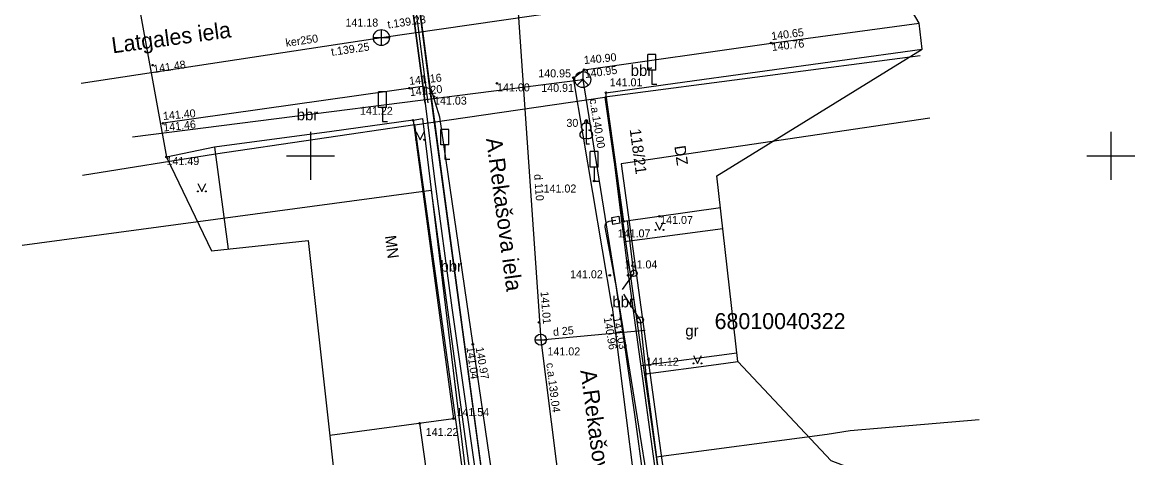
# Model space of a CAD drawing. Extents: x 728710 to 728960, y 272811 to 273475.
# Drawn here: x 728782 to 728851.5, y 273131.1 to 273158.4 of the extents above; entities that cross this region are included whole.
import ezdxf

# ---------------------------------------------------------------- set-up
doc = ezdxf.new("R2010")
doc.units = 0
for name, color, linetype in [('54', 7, 'Continuous'), ('58', 7, 'Continuous'), ('GEOD_ELEM_####_TKST_#', 7, 'Continuous'), ('Level 10', 7, 'Continuous'), ('Level 15', 7, 'Continuous'), ('Level 17', 7, 'Continuous'), ('Level 23', 7, 'Continuous'), ('Level 27', 7, 'Continuous'), ('Level 29', 7, 'Continuous'), ('Level 3', 7, 'Continuous'), ('Level 36', 7, 'Continuous'), ('Level 38', 7, 'Continuous'), ('Level 39', 7, 'Continuous'), ('Level 4', 7, 'Continuous'), ('Level 41', 7, 'Continuous'), ('Level 43', 7, 'Continuous'), ('Level 46', 7, 'Continuous'), ('Level 48', 7, 'Continuous'), ('Level 49', 7, 'Continuous'), ('Level 54', 7, 'Continuous'), ('Level 55', 7, 'Continuous'), ('Level 56', 7, 'Continuous'), ('Level 57', 7, 'Continuous'), ('Level 58', 7, 'Continuous'), ('Level 59', 7, 'Continuous'), ('Level 60', 7, 'Continuous'), ('Level 62', 7, 'Continuous'), ('PNTNO', 7, 'Continuous'), ('RAMI_UZMR_####_####_#', 7, 'Continuous'), ('RELJ_ELEM_####_####_#', 7, 'Continuous'), ('RELJ_NOGA_####_####_#', 7, 'Continuous'), ('ROBZ_ELEM_####_####_#', 7, 'Continuous'), ('ROBZ_KADS_####_TKST_#', 7, 'Continuous'), ('ROBZ_UZMR_####_####_#', 7, 'Continuous'), ('TERT_ELEM_####_####_#', 7, 'Continuous'), ('TERT_KONT_####_####_#', 7, 'Continuous')]:
    doc.layers.add(name, color=color, linetype=linetype)

msp = doc.modelspace()

# ---------------------------------------------------------------- linework, layer by layer
at = {"layer": 'GEOD_ELEM_####_TKST_#'}
msp.add_lwpolyline([(728812.551, 273107.084), (728813.681, 273107.292), (728813.683, 273107.676), (728812.175, 273119.32), (728807.481, 273154.061), (728806.142, 273164.357), (728806.065, 273164.722), (728806.247, 273164.866), (728807.003, 273165.091)], dxfattribs=at)
at = {"layer": 'Level 10'}
for p, q in [((728800, 273151.5), (728800, 273150)), ((728850, 273151.5), (728850, 273150)), ((728798.5, 273150), (728800, 273150)), ((728800, 273150), (728800, 273148.5)), ((728800, 273150), (728801.5, 273150)), ((728848.5, 273150), (728850, 273150)), ((728850, 273150), (728850, 273148.5)), ((728850, 273150), (728851.5, 273150))]:
    msp.add_line(p, q, dxfattribs=at)
at = {"layer": 'Level 15'}
msp.add_lwpolyline([(728819.334, 273145.797), (728818.894, 273145.717), (728818.816, 273146.149), (728819.256, 273146.229)], close=True, dxfattribs=at)
at = {"layer": 'Level 17'}
msp.add_line((728814.387, 273138.519), (728820.906, 273139.113), dxfattribs=at)
for points in [[(728812.761, 273161.966), (728814.387, 273138.519)], [(728814.387, 273138.519), (728819.492, 273098.009)]]:
    msp.add_lwpolyline(points, dxfattribs=at)
at = {"layer": 'Level 23'}
msp.add_lwpolyline([(728785.659, 273154.554), (728804.423, 273157.397), (728830.532, 273161.186)], dxfattribs=at)
at = {"layer": 'Level 27'}
for points in [[(728820.21, 273142.669), (728819.812, 273145.946)], [(728820.595, 273139.749), (728820.949, 273136.385)]]:
    msp.add_lwpolyline(points, dxfattribs=at)
at = {"layer": 'Level 29'}
for p, q in [((728803.923, 273157.397), (728804.923, 273157.397)), ((728804.423, 273156.897), (728804.423, 273157.897))]:
    msp.add_line(p, q, dxfattribs=at)
msp.add_circle((728804.423, 273157.397), 0.5, dxfattribs=at)
at = {"layer": 'Level 3'}
for p, q in [((728822.792, 273154.55), (728838.211, 273156.68)), ((728818.457, 273153.951), (728822.792, 273154.55)), ((728819.568, 273145.912), (728818.457, 273153.951)), ((728806.402, 273152.228), (728801.322, 273151.539)), ((728806.402, 273152.228), (728808.931, 273133.58)), ((728801.322, 273151.539), (728793.998, 273150.545)), ((728793.998, 273150.545), (728794.861, 273144.179)), ((728825.616, 273146.748), (728819.568, 273145.912)), ((728820.949, 273136.385), (728825.344, 273136.966)), ((728825.344, 273136.966), (728826.701, 273137.145)), ((728822.25, 273126.539), (728820.949, 273136.385)), ((728808.931, 273133.58), (728801.201, 273132.532)), ((728806.814, 273133.293), (728808.351, 273122.364))]:
    msp.add_line(p, q, dxfattribs=at)
at = {"layer": 'Level 36'}
msp.add_line((728807.355, 273153.329), (728806.056, 273163.207), dxfattribs=at)
for points in [[(728807.157, 273153.303), (728805.858, 273163.181)], [(728818.916, 273142.762), (728819.077, 273141.897), (728820.259, 273133.689), (728821.3, 273126.022), (728821.336, 273125.784), (728822.279, 273119.148)]]:
    msp.add_lwpolyline(points, dxfattribs=at)
at = {"layer": 'Level 38'}
for p, q in [((728828.784, 273157.056), (728838.026, 273158.297)), ((728817.1, 273155.387), (728828.784, 273157.056)), ((728806.989, 273154.338), (728790.784, 273152.04))]:
    msp.add_line(p, q, dxfattribs=at)
at = {"layer": 'Level 39'}
for p, q in [((728814.036, 273138.519), (728814.738, 273138.519)), ((728814.386, 273138.519), (728814.386, 273138.52))]:
    msp.add_line(p, q, dxfattribs=at)
msp.add_circle((728814.387, 273138.519), 0.351, dxfattribs=at)
at = {"layer": 'Level 4'}
for p, q in [((728816.423, 273154.886), (728817.1, 273155.387)), ((728818.846, 273140.542), (728816.423, 273154.886)), ((728819.87, 273142.614), (728818.457, 273153.951)), ((728806.402, 273152.228), (728807.002, 273152.348)), ((728807.002, 273152.348), (728810.246, 273125.587)), ((728793.998, 273150.545), (728790.999, 273149.932)), ((728819.616, 273144.651), (728825.761, 273145.463)), ((728823.17, 273118.565), (728819.87, 273142.614)), ((728820.652, 273136.912), (728826.638, 273137.702))]:
    msp.add_line(p, q, dxfattribs=at)
for points in [[(728811.836, 273126.782), (728808.082, 273152.433), (728807.534, 273154.175), (728806.989, 273154.338)], [(728818.846, 273140.542), (728820.596, 273126.711), (728822.052, 273116.462)]]:
    msp.add_lwpolyline(points, dxfattribs=at)
at = {"layer": 'Level 41'}
msp.add_lwpolyline([(728788.876, 273151.188), (728817.008, 273154.772), (728824.535, 273107.953), (728843.792, 273111.191)], dxfattribs=at)
at = {"layer": 'Level 43'}
for p, q in [((728820.21, 273142.669), (728819.481, 273141.65)), ((728820.595, 273139.749), (728819.57, 273141.357))]:
    msp.add_line(p, q, dxfattribs=at)
for centre in [(728820.21, 273142.669), (728820.595, 273139.749)]:
    msp.add_circle(centre, 0.202, dxfattribs=at)
at = {"layer": 'Level 46'}
msp.add_line((728817.008, 273154.772), (728817.362, 273154.418), dxfattribs=at)
msp.add_lwpolyline([(728817.008, 273155.272), (728817.008, 273154.772), (728816.654, 273154.418)], dxfattribs=at)
msp.add_circle((728817.008, 273154.772), 0.5, dxfattribs=at)
at = {"layer": 'Level 48'}
for centre in [(728828.784, 273157.056), (728790.133, 273155.674), (728817.1, 273155.387), (728811.656, 273154.535), (728816.423, 273154.886), (728817.008, 273154.772), (728806.177, 273154.237), (728818.457, 273153.951), (728807.716, 273153.708), (728790.784, 273152.04), (728806.402, 273152.228), (728790.999, 273149.932), (728817.719, 273148.429), (728821.801, 273146.221), (728819.568, 273145.912), (728818.698, 273142.537), (728819.847, 273142.537), (728818.846, 273140.041), (728814.273, 273139.597), (728810.141, 273138.225), (728820.949, 273136.385), (728806.814, 273133.293), (728808.931, 273133.58)]:
    msp.add_circle(centre, 0.05, dxfattribs=at)
at = {"layer": 'Level 49'}
for p, q in [((728821.572, 273156.338), (728821.072, 273156.338)), ((728821.072, 273155.369), (728821.072, 273156.338)), ((728821.572, 273155.369), (728821.572, 273156.338)), ((728821.572, 273155.369), (728821.072, 273155.369)), ((728821.326, 273155.369), (728821.326, 273154.491)), ((728804.737, 273154.004), (728804.237, 273154.004)), ((728804.237, 273153.035), (728804.237, 273154.004)), ((728804.737, 273153.035), (728804.737, 273154.004)), ((728821.326, 273154.491), (728821.641, 273154.491)), ((728804.737, 273153.035), (728804.237, 273153.035)), ((728804.491, 273153.035), (728804.491, 273152.157)), ((728804.491, 273152.157), (728804.806, 273152.157)), ((728808.631, 273151.655), (728808.131, 273151.655)), ((728808.131, 273150.686), (728808.131, 273151.655)), ((728808.631, 273150.686), (728808.631, 273151.655)), ((728808.631, 273150.686), (728808.131, 273150.686)), ((728808.385, 273150.686), (728808.385, 273149.808)), ((728808.385, 273149.808), (728808.7, 273149.808)), ((728817.965, 273150.276), (728817.465, 273150.276)), ((728817.465, 273149.307), (728817.465, 273150.276)), ((728817.965, 273149.307), (728817.965, 273150.276)), ((728817.965, 273149.307), (728817.465, 273149.307)), ((728817.719, 273149.307), (728817.719, 273148.429)), ((728817.719, 273148.429), (728818.034, 273148.429))]:
    msp.add_line(p, q, dxfattribs=at)
at = {"layer": 'RAMI_UZMR_####_####_#'}
for points in [[(728848.126, 273018.981), (728842.745, 273067.512), (728841.027, 273070.984), (728840.357, 273077.286), (728837.229, 273086.616), (728846.28, 273097.37), (728843.445, 273113.117), (728841.542, 273127.507), (728832.527, 273130.942), (728826.701, 273137.145), (728825.388, 273148.763), (728838.211, 273156.68), (728838.026, 273158.297), (728833.202, 273166.507)], [(728788.892, 273161.497), (728790.999, 273149.932), (728793.805, 273144.064), (728799.858, 273144.727), (728801.765, 273127.417), (728785.623, 273117.349), (728785.888, 273114.234), (728788.818, 273102.829), (728792.114, 273090.001), (728794.527, 273084.256), (728808.426, 273087.287), (728810.894, 273070.336), (728816.634, 273032.011)]]:
    msp.add_lwpolyline(points, dxfattribs=at)
at = {"layer": 'RELJ_ELEM_####_####_#'}
msp.add_lwpolyline([(728807.003, 273165.091), (728806.309, 273164.885), (728806.073, 273164.759), (728806.082, 273164.765), (728806.142, 273164.357), (728807.497, 273153.999), (728812.666, 273115.604), (728813.66, 273107.967), (728813.707, 273107.385), (728813.681, 273107.292), (728813.602, 273107.257), (728812.551, 273107.084)], dxfattribs=at)
at = {"layer": 'ROBZ_ELEM_####_####_#'}
for points in [[(728838.703, 273152.369), (728819.408, 273149.515)], [(728819.408, 273149.515), (728824.842, 273109.886)], [(728807.526, 273147.836), (728781.985, 273144.395)], [(728807.526, 273147.836), (728813.011, 273107.831)]]:
    msp.add_lwpolyline(points, dxfattribs=at)
at = {"layer": 'ROBZ_UZMR_####_####_#'}
for p, q in [((728838.082, 273156.252), (728818.395, 273153.682)), ((728806.506, 273151.952), (728818.395, 273153.682)), ((728818.395, 273153.682), (728819.556, 273145.531)), ((728806.506, 273151.952), (728794.058, 273150.104)), ((728809.109, 273133.219), (728806.506, 273151.952)), ((728794.058, 273150.104), (728785.756, 273148.773)), ((728819.556, 273145.531), (728821.586, 273131.187)), ((728812.63, 273106.926), (728809.109, 273133.219)), ((728833.717, 273132.846), (728841.771, 273133.527)), ((728821.586, 273131.187), (728832.287, 273132.612)), ((728832.287, 273132.612), (728833.717, 273132.846)), ((728821.586, 273131.187), (728822.26, 273126.26))]:
    msp.add_line(p, q, dxfattribs=at)
at = {"layer": 'TERT_ELEM_####_####_#'}
for points in [[(728805.858, 273163.181), (728807.157, 273153.303)], [(728807.157, 273153.303), (728807.729, 273148.716), (728808.834, 273140.506), (728809.798, 273133.659), (728810.998, 273125.369), (728811.313, 273123.197)], [(728818.397, 273145.555), (728819.077, 273141.897), (728820.259, 273133.689), (728821.3, 273126.022), (728822.228, 273119.505)], [(728819.075, 273145.973), (728818.646, 273145.906)]]:
    msp.add_lwpolyline(points, dxfattribs=at)
msp.add_arc((728818.692, 273145.609), 0.3, 98.90447, 190.52618, dxfattribs=at)
at = {"layer": 'TERT_KONT_####_####_#'}
for p, q in [((728806.605, 273151.515), (728806.855, 273151.015)), ((728806.855, 273151.015), (728807.105, 273151.515)), ((728817.229, 273151.113), (728817.229, 273150.766)), ((728817.229, 273150.766), (728817.429, 273150.766)), ((728792.955, 273148.287), (728793.205, 273147.787)), ((728793.205, 273147.787), (728793.455, 273148.287)), ((728821.548, 273145.879), (728821.798, 273145.379)), ((728821.798, 273145.379), (728822.048, 273145.879)), ((728823.92, 273137.539), (728824.17, 273137.039)), ((728824.17, 273137.039), (728824.42, 273137.539))]:
    msp.add_line(p, q, dxfattribs=at)
for points in [[(728817.229, 273152.266), (728817.229, 273151.113)], [(728817.319, 273152.034), (728817.318, 273152.035)]]:
    msp.add_lwpolyline(points, dxfattribs=at)
for centre, radius in [((728806.605, 273151.015), 0.028), ((728807.105, 273151.015), 0.0263), ((728792.955, 273147.787), 0.028), ((728793.455, 273147.787), 0.0263), ((728821.548, 273145.378), 0.028), ((728822.048, 273145.378), 0.0263), ((728823.92, 273137.038), 0.028), ((728824.42, 273137.038), 0.0263)]:
    msp.add_circle(centre, radius, dxfattribs=at)
for centre, major_axis, ratio, start_param, end_param in [((728817.101, 273151.821), (-0.039, -0.212), 0.861323, 3.141593, 6.283185), ((728817.229, 273152.116), (0, -0.15), 0.707107, 3.14537, 5.287485), ((728817.229, 273152.116), (0, -0.15), 0.707107, 0.995701, 3.137816), ((728817.357, 273151.821), (0.039, -0.212), 0.861323, 0, 3.141593), ((728817.139, 273151.359), (0.307, 0.095), 0.814445, 1.570796, 4.752015), ((728817.319, 273151.359), (-0.307, 0.095), 0.814445, 1.531171, 4.712389)]:
    msp.add_ellipse(centre, major_axis=major_axis, ratio=ratio, start_param=start_param, end_param=end_param, dxfattribs=at)

# ---------------------------------------------------------------- texts
at = {"layer": '54'}
msp.add_text('c.a.140.00', height=0.5, rotation=279.13318, dxfattribs=at).set_placement((728817.428, 273153.529))
at = {"layer": '58'}
msp.add_text(' 140.95', height=0.5, dxfattribs=at).set_placement((728814.044, 273154.913))
at = {"layer": 'Level 54'}
for s, rotation, p in [('Latgales iela', 7.723, (728787.637, 273156.409)), ('A.Rekašova iela', 277.641, (728810.965, 273151.073)), ('A.Rekašova iela', 277.641, (728816.855, 273136.586))]:
    msp.add_text(s, height=1, rotation=rotation, dxfattribs=at).set_placement(p)
at = {"layer": 'Level 55'}
for s, rotation, p in [('d 110', 273.96699, (728813.971, 273148.847)), ('d 25', 5.20632, (728815.17, 273138.749)), ('c.a.139.04', 277.18245, (728814.724, 273137.044))]:
    msp.add_text(s, height=0.5, rotation=rotation, dxfattribs=at).set_placement(p)
at = {"layer": 'Level 56'}
msp.add_text(' 141.18', height=0.5, dxfattribs=at).set_placement((728801.997, 273158.086))
at = {"layer": 'Level 57'}
for s, rotation, p in [('140.65', 7.28083, (728828.82, 273157.238)), ('140.76', 6.56448, (728828.841, 273156.559)), ('141.48', 8.61156, (728790.208, 273155.18)), ('140.90', 5.44471, (728817.101, 273155.742)), ('140.95', 7.83534, (728817.166, 273154.864)), ('141.16', 6.10769, (728806.182, 273154.438)), ('141.20', 5.8857, (728806.222, 273153.736)), ('141.40', 5.0837, (728790.799, 273152.247)), ('141.46', 6.16242, (728790.823, 273151.525)), ('141.01', 274.5599, (728814.369, 273141.515)), ('140.96', 279.69895, (728818.314, 273139.875)), ('141.03', 282.06435, (728818.87, 273139.883)), ('141.04', 277.94442, (728809.743, 273138.041)), ('140.97', 279.92477, (728810.312, 273138.015))]:
    msp.add_text(s, height=0.5, rotation=rotation, dxfattribs=at).set_placement(p)
for s, p in [(' 141.01', (728818.506, 273154.352)), ('141.00', (728811.656, 273154.035)), ('140.91', (728814.413, 273154.007)), ('141.03', (728807.716, 273153.208)), (' 141.22', (728802.903, 273152.572)), ('141.49', (728790.999, 273149.432)), (' 141.02', (728814.376, 273147.715)), (' 141.07', (728821.661, 273145.749)), (' 141.07', (728819.006, 273144.912)), (' 141.04', (728819.44, 273142.972)), (' 141.02', (728816.031, 273142.357)), (' 141.12', (728820.774, 273136.891)), (' 141.54', (728808.93, 273133.741)), (' 141.22', (728807.011, 273132.499))]:
    msp.add_text(s, height=0.5, dxfattribs=at).set_placement(p)
at = {"layer": 'Level 58'}
for s, p in [('bbr', (728819.999, 273154.996)), ('bbr', (728799.133, 273152.231)), ('bbr', (728808.117, 273142.767)), ('bbr', (728818.856, 273140.537)), ('gr', (728823.417, 273138.734))]:
    msp.add_text(s, height=0.7, dxfattribs=at).set_placement(p)
at = {"layer": 'Level 59'}
for s, rotation, p in [('DZ', 277.866, (728822.73, 273150.604)), ('MN', 277.723, (728804.642, 273144.992))]:
    msp.add_text(s, height=0.7, rotation=rotation, dxfattribs=at).set_placement(p)
at = {"layer": 'Level 60'}
for s, p in [('t.139.23', (728804.84, 273157.963)), ('ker250', (728798.476, 273156.82)), ('t.139.25', (728801.322, 273156.252))]:
    msp.add_text(s, height=0.5, rotation=8.258, dxfattribs=at).set_placement(p)
at = {"layer": 'Level 62'}
msp.add_text('118/21', height=0.7, rotation=277.866, dxfattribs=at).set_placement((728819.936, 273151.657))
at = {"layer": 'PNTNO'}
msp.add_text(' 141.02', height=0.5, dxfattribs=at).set_placement((728814.619, 273137.537))
at = {"layer": 'RELJ_NOGA_####_####_#'}
msp.add_text('30', height=0.5, dxfattribs=at).set_placement((728815.988, 273151.817))
at = {"layer": 'ROBZ_KADS_####_TKST_#'}
msp.add_text('68010040322', height=1, dxfattribs=at).set_placement((728825.247, 273139.181))

doc.saveas('drawing.dxf')
